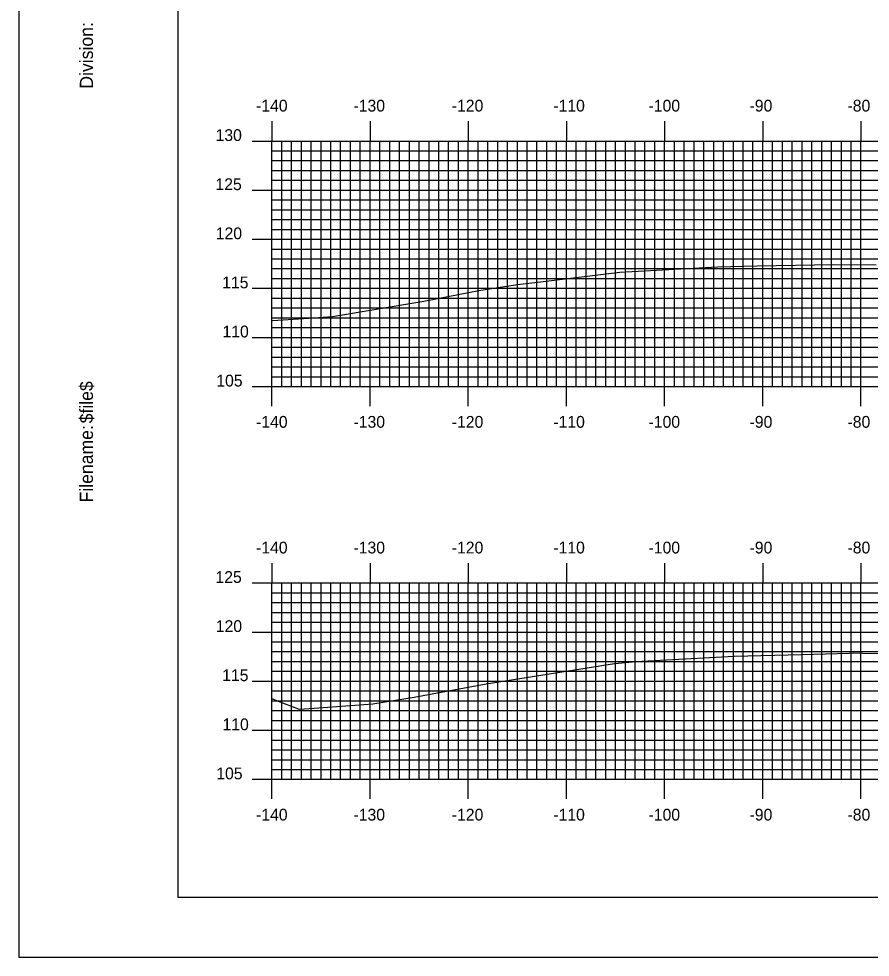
# Model space of a CAD drawing. Extents: x 855468 to 855811, y 366605 to 366825.
# Drawn here: x 855467.8 to 855554.5, y 366604.9 to 366700.5 of the extents above; entities that cross this region are included whole.
import ezdxf

# ---------------------------------------------------------------- set-up
doc = ezdxf.new("R2010")
doc.units = 0
for name, color, linetype in [('BORDER', 7, 'Continuous'), ('H_V ANNOTATION', 7, 'Continuous'), ('M_Roadway_Centerline', 7, 'Continuous'), ('MAJOR', 7, 'Continuous'), ('MINOR', 7, 'Continuous'), ('PLOT BOUNDARY', 7, 'Continuous'), ('S_Roadway_Centerline', 7, 'Continuous')]:
    doc.layers.add(name, color=color, linetype=linetype)

msp = doc.modelspace()

# ---------------------------------------------------------------- linework, layer by layer
at = {"layer": 'BORDER'}
msp.add_lwpolyline([(855483.982, 366611.055), (855803.982, 366611.055), (855803.982, 366821.055), (855483.982, 366821.055)], close=True, dxfattribs=at)
at = {"layer": 'MAJOR'}
for p, q in [((855493.582, 366690.059), (855493.582, 366688.055)), ((855503.582, 366690.059), (855503.582, 366688.055)), ((855513.582, 366690.059), (855513.582, 366688.055)), ((855523.582, 366690.059), (855523.582, 366688.055)), ((855533.582, 366690.059), (855533.582, 366688.055)), ((855543.582, 366690.059), (855543.582, 366688.055)), ((855553.582, 366690.059), (855553.582, 366688.055)), ((855491.578, 366688.055), (855493.582, 366688.055)), ((855493.582, 366688.055), (855773.582, 366688.055)), ((855493.582, 366663.055), (855493.582, 366688.055)), ((855493.582, 366663.055), (855493.582, 366688.055)), ((855493.582, 366688.055), (855773.582, 366688.055)), ((855503.582, 366663.055), (855503.582, 366688.055)), ((855513.582, 366663.055), (855513.582, 366688.055)), ((855523.582, 366663.055), (855523.582, 366688.055)), ((855533.582, 366663.055), (855533.582, 366688.055)), ((855543.582, 366663.055), (855543.582, 366688.055)), ((855553.582, 366663.055), (855553.582, 366688.055)), ((855491.578, 366683.055), (855493.582, 366683.055)), ((855493.582, 366683.055), (855773.582, 366683.055)), ((855491.578, 366678.055), (855493.582, 366678.055)), ((855493.582, 366678.055), (855773.582, 366678.055)), ((855491.578, 366673.055), (855493.582, 366673.055)), ((855493.582, 366673.055), (855773.582, 366673.055)), ((855491.578, 366668.055), (855493.582, 366668.055)), ((855493.582, 366668.055), (855773.582, 366668.055)), ((855491.578, 366663.055), (855493.582, 366663.055)), ((855493.582, 366663.055), (855773.582, 366663.055)), ((855493.582, 366663.055), (855773.582, 366663.055)), ((855493.582, 366661.051), (855493.582, 366663.055)), ((855503.582, 366661.051), (855503.582, 366663.055)), ((855513.582, 366661.051), (855513.582, 366663.055)), ((855523.582, 366661.051), (855523.582, 366663.055)), ((855533.582, 366661.051), (855533.582, 366663.055)), ((855543.582, 366661.051), (855543.582, 366663.055)), ((855553.582, 366661.051), (855553.582, 366663.055)), ((855493.582, 366645.059), (855493.582, 366643.055)), ((855503.582, 366645.059), (855503.582, 366643.055)), ((855513.582, 366645.059), (855513.582, 366643.055)), ((855523.582, 366645.059), (855523.582, 366643.055)), ((855533.582, 366645.059), (855533.582, 366643.055)), ((855543.582, 366645.059), (855543.582, 366643.055)), ((855553.582, 366645.059), (855553.582, 366643.055)), ((855491.578, 366643.055), (855493.582, 366643.055)), ((855493.582, 366643.055), (855773.582, 366643.055)), ((855493.582, 366623.055), (855493.582, 366643.055)), ((855493.582, 366623.055), (855493.582, 366643.055)), ((855493.582, 366643.055), (855773.582, 366643.055)), ((855503.582, 366623.055), (855503.582, 366643.055)), ((855513.582, 366623.055), (855513.582, 366643.055)), ((855523.582, 366623.055), (855523.582, 366643.055)), ((855533.582, 366623.055), (855533.582, 366643.055)), ((855543.582, 366623.055), (855543.582, 366643.055)), ((855553.582, 366623.055), (855553.582, 366643.055)), ((855491.578, 366638.055), (855493.582, 366638.055)), ((855493.582, 366638.055), (855773.582, 366638.055)), ((855491.578, 366633.055), (855493.582, 366633.055)), ((855493.582, 366633.055), (855773.582, 366633.055)), ((855491.578, 366628.055), (855493.582, 366628.055)), ((855493.582, 366628.055), (855773.582, 366628.055)), ((855491.578, 366623.055), (855493.582, 366623.055)), ((855493.582, 366623.055), (855773.582, 366623.055)), ((855493.582, 366623.055), (855773.582, 366623.055)), ((855493.582, 366621.051), (855493.582, 366623.055)), ((855503.582, 366621.051), (855503.582, 366623.055)), ((855513.582, 366621.051), (855513.582, 366623.055)), ((855523.582, 366621.051), (855523.582, 366623.055)), ((855533.582, 366621.051), (855533.582, 366623.055)), ((855543.582, 366621.051), (855543.582, 366623.055)), ((855553.582, 366621.051), (855553.582, 366623.055))]:
    msp.add_line(p, q, dxfattribs=at)
at = {"layer": 'MINOR'}
for p, q in [((855494.582, 366663.055), (855494.582, 366688.055)), ((855495.582, 366663.055), (855495.582, 366688.055)), ((855496.582, 366663.055), (855496.582, 366688.055)), ((855497.582, 366663.055), (855497.582, 366688.055)), ((855498.582, 366663.055), (855498.582, 366688.055)), ((855499.582, 366663.055), (855499.582, 366688.055)), ((855500.582, 366663.055), (855500.582, 366688.055)), ((855501.582, 366663.055), (855501.582, 366688.055)), ((855502.582, 366663.055), (855502.582, 366688.055)), ((855504.582, 366663.055), (855504.582, 366688.055)), ((855505.582, 366663.055), (855505.582, 366688.055)), ((855506.582, 366663.055), (855506.582, 366688.055)), ((855507.582, 366663.055), (855507.582, 366688.055)), ((855508.582, 366663.055), (855508.582, 366688.055)), ((855509.582, 366663.055), (855509.582, 366688.055)), ((855510.582, 366663.055), (855510.582, 366688.055)), ((855511.582, 366663.055), (855511.582, 366688.055)), ((855512.582, 366663.055), (855512.582, 366688.055)), ((855514.582, 366663.055), (855514.582, 366688.055)), ((855515.582, 366663.055), (855515.582, 366688.055)), ((855516.582, 366663.055), (855516.582, 366688.055)), ((855517.582, 366663.055), (855517.582, 366688.055)), ((855518.582, 366663.055), (855518.582, 366688.055)), ((855519.582, 366663.055), (855519.582, 366688.055)), ((855520.582, 366663.055), (855520.582, 366688.055)), ((855521.582, 366663.055), (855521.582, 366688.055)), ((855522.582, 366663.055), (855522.582, 366688.055)), ((855524.582, 366663.055), (855524.582, 366688.055)), ((855525.582, 366663.055), (855525.582, 366688.055)), ((855526.582, 366663.055), (855526.582, 366688.055)), ((855527.582, 366663.055), (855527.582, 366688.055)), ((855528.582, 366663.055), (855528.582, 366688.055)), ((855529.582, 366663.055), (855529.582, 366688.055)), ((855530.582, 366663.055), (855530.582, 366688.055)), ((855531.582, 366663.055), (855531.582, 366688.055)), ((855532.582, 366663.055), (855532.582, 366688.055)), ((855534.582, 366663.055), (855534.582, 366688.055)), ((855535.582, 366663.055), (855535.582, 366688.055)), ((855536.582, 366663.055), (855536.582, 366688.055)), ((855537.582, 366663.055), (855537.582, 366688.055)), ((855538.582, 366663.055), (855538.582, 366688.055)), ((855539.582, 366663.055), (855539.582, 366688.055)), ((855540.582, 366663.055), (855540.582, 366688.055)), ((855541.582, 366663.055), (855541.582, 366688.055)), ((855542.582, 366663.055), (855542.582, 366688.055)), ((855544.582, 366663.055), (855544.582, 366688.055)), ((855545.582, 366663.055), (855545.582, 366688.055)), ((855546.582, 366663.055), (855546.582, 366688.055)), ((855547.582, 366663.055), (855547.582, 366688.055)), ((855548.582, 366663.055), (855548.582, 366688.055)), ((855549.582, 366663.055), (855549.582, 366688.055)), ((855550.582, 366663.055), (855550.582, 366688.055)), ((855551.582, 366663.055), (855551.582, 366688.055)), ((855552.582, 366663.055), (855552.582, 366688.055)), ((855493.582, 366687.055), (855773.582, 366687.055)), ((855493.582, 366687.055), (855495.586, 366687.055)), ((855493.582, 366686.055), (855773.582, 366686.055)), ((855493.582, 366686.055), (855495.586, 366686.055)), ((855493.582, 366685.055), (855773.582, 366685.055)), ((855493.582, 366685.055), (855495.586, 366685.055)), ((855493.582, 366684.055), (855773.582, 366684.055)), ((855493.582, 366684.055), (855495.586, 366684.055)), ((855493.582, 366682.055), (855773.582, 366682.055)), ((855493.582, 366682.055), (855495.586, 366682.055)), ((855493.582, 366681.055), (855773.582, 366681.055)), ((855493.582, 366681.055), (855495.586, 366681.055)), ((855493.582, 366680.055), (855773.582, 366680.055)), ((855493.582, 366680.055), (855495.586, 366680.055)), ((855493.582, 366679.055), (855773.582, 366679.055)), ((855493.582, 366679.055), (855495.586, 366679.055)), ((855493.582, 366677.055), (855773.582, 366677.055)), ((855493.582, 366677.055), (855495.586, 366677.055)), ((855493.582, 366676.055), (855773.582, 366676.055)), ((855493.582, 366676.055), (855495.586, 366676.055)), ((855493.582, 366675.055), (855773.582, 366675.055)), ((855493.582, 366675.055), (855495.586, 366675.055)), ((855493.582, 366674.055), (855773.582, 366674.055)), ((855493.582, 366674.055), (855495.586, 366674.055)), ((855493.582, 366672.055), (855773.582, 366672.055)), ((855493.582, 366672.055), (855495.586, 366672.055)), ((855493.582, 366671.055), (855773.582, 366671.055)), ((855493.582, 366671.055), (855495.586, 366671.055)), ((855493.582, 366670.055), (855773.582, 366670.055)), ((855493.582, 366670.055), (855495.586, 366670.055)), ((855493.582, 366669.055), (855773.582, 366669.055)), ((855493.582, 366669.055), (855495.586, 366669.055)), ((855493.582, 366667.055), (855773.582, 366667.055)), ((855493.582, 366667.055), (855495.586, 366667.055)), ((855493.582, 366666.055), (855773.582, 366666.055)), ((855493.582, 366666.055), (855495.586, 366666.055)), ((855493.582, 366665.055), (855773.582, 366665.055)), ((855493.582, 366665.055), (855495.586, 366665.055)), ((855493.582, 366664.055), (855773.582, 366664.055)), ((855493.582, 366664.055), (855495.586, 366664.055)), ((855494.582, 366623.055), (855494.582, 366643.055)), ((855495.582, 366623.055), (855495.582, 366643.055)), ((855496.582, 366623.055), (855496.582, 366643.055)), ((855497.582, 366623.055), (855497.582, 366643.055)), ((855498.582, 366623.055), (855498.582, 366643.055)), ((855499.582, 366623.055), (855499.582, 366643.055)), ((855500.582, 366623.055), (855500.582, 366643.055)), ((855501.582, 366623.055), (855501.582, 366643.055)), ((855502.582, 366623.055), (855502.582, 366643.055)), ((855504.582, 366623.055), (855504.582, 366643.055)), ((855505.582, 366623.055), (855505.582, 366643.055)), ((855506.582, 366623.055), (855506.582, 366643.055)), ((855507.582, 366623.055), (855507.582, 366643.055)), ((855508.582, 366623.055), (855508.582, 366643.055)), ((855509.582, 366623.055), (855509.582, 366643.055)), ((855510.582, 366623.055), (855510.582, 366643.055)), ((855511.582, 366623.055), (855511.582, 366643.055)), ((855512.582, 366623.055), (855512.582, 366643.055)), ((855514.582, 366623.055), (855514.582, 366643.055)), ((855515.582, 366623.055), (855515.582, 366643.055)), ((855516.582, 366623.055), (855516.582, 366643.055)), ((855517.582, 366623.055), (855517.582, 366643.055)), ((855518.582, 366623.055), (855518.582, 366643.055)), ((855519.582, 366623.055), (855519.582, 366643.055)), ((855520.582, 366623.055), (855520.582, 366643.055)), ((855521.582, 366623.055), (855521.582, 366643.055)), ((855522.582, 366623.055), (855522.582, 366643.055)), ((855524.582, 366623.055), (855524.582, 366643.055)), ((855525.582, 366623.055), (855525.582, 366643.055)), ((855526.582, 366623.055), (855526.582, 366643.055)), ((855527.582, 366623.055), (855527.582, 366643.055)), ((855528.582, 366623.055), (855528.582, 366643.055)), ((855529.582, 366623.055), (855529.582, 366643.055)), ((855530.582, 366623.055), (855530.582, 366643.055)), ((855531.582, 366623.055), (855531.582, 366643.055)), ((855532.582, 366623.055), (855532.582, 366643.055)), ((855534.582, 366623.055), (855534.582, 366643.055)), ((855535.582, 366623.055), (855535.582, 366643.055)), ((855536.582, 366623.055), (855536.582, 366643.055)), ((855537.582, 366623.055), (855537.582, 366643.055)), ((855538.582, 366623.055), (855538.582, 366643.055)), ((855539.582, 366623.055), (855539.582, 366643.055)), ((855540.582, 366623.055), (855540.582, 366643.055)), ((855541.582, 366623.055), (855541.582, 366643.055)), ((855542.582, 366623.055), (855542.582, 366643.055)), ((855544.582, 366623.055), (855544.582, 366643.055)), ((855545.582, 366623.055), (855545.582, 366643.055)), ((855546.582, 366623.055), (855546.582, 366643.055)), ((855547.582, 366623.055), (855547.582, 366643.055)), ((855548.582, 366623.055), (855548.582, 366643.055)), ((855549.582, 366623.055), (855549.582, 366643.055)), ((855550.582, 366623.055), (855550.582, 366643.055)), ((855551.582, 366623.055), (855551.582, 366643.055)), ((855552.582, 366623.055), (855552.582, 366643.055)), ((855493.582, 366642.055), (855773.582, 366642.055)), ((855493.582, 366642.055), (855495.586, 366642.055)), ((855493.582, 366641.055), (855773.582, 366641.055)), ((855493.582, 366641.055), (855495.586, 366641.055)), ((855493.582, 366640.055), (855773.582, 366640.055)), ((855493.582, 366640.055), (855495.586, 366640.055)), ((855493.582, 366639.055), (855773.582, 366639.055)), ((855493.582, 366639.055), (855495.586, 366639.055)), ((855493.582, 366637.055), (855773.582, 366637.055)), ((855493.582, 366637.055), (855495.586, 366637.055)), ((855493.582, 366636.055), (855773.582, 366636.055)), ((855493.582, 366636.055), (855495.586, 366636.055)), ((855493.582, 366635.055), (855773.582, 366635.055)), ((855493.582, 366635.055), (855495.586, 366635.055)), ((855493.582, 366634.055), (855773.582, 366634.055)), ((855493.582, 366634.055), (855495.586, 366634.055)), ((855493.582, 366632.055), (855773.582, 366632.055)), ((855493.582, 366632.055), (855495.586, 366632.055)), ((855493.582, 366631.055), (855773.582, 366631.055)), ((855493.582, 366631.055), (855495.586, 366631.055)), ((855493.582, 366630.055), (855773.582, 366630.055)), ((855493.582, 366630.055), (855495.586, 366630.055)), ((855493.582, 366629.055), (855773.582, 366629.055)), ((855493.582, 366629.055), (855495.586, 366629.055)), ((855493.582, 366627.055), (855773.582, 366627.055)), ((855493.582, 366627.055), (855495.586, 366627.055)), ((855493.582, 366626.055), (855773.582, 366626.055)), ((855493.582, 366626.055), (855495.586, 366626.055)), ((855493.582, 366625.055), (855773.582, 366625.055)), ((855493.582, 366625.055), (855495.586, 366625.055)), ((855493.582, 366624.055), (855773.582, 366624.055)), ((855493.582, 366624.055), (855495.586, 366624.055))]:
    msp.add_line(p, q, dxfattribs=at)
at = {"layer": 'PLOT BOUNDARY'}
msp.add_lwpolyline([(855467.796, 366604.937), (855807.796, 366604.937), (855807.796, 366824.937), (855467.796, 366824.937)], close=True, dxfattribs=at)
at = {"layer": 'S_Roadway_Centerline'}
for points in [[(855493.582, 366669.805), (855493.673, 366669.78), (855497.861, 366670.036), (855499.763, 366670.2), (855509.051, 366671.735), (855514.665, 366672.833), (855518.612, 366673.444), (855520.933, 366673.715), (855529.005, 366674.715), (855538.361, 366675.21), (855538.954, 366675.247), (855543.005, 366675.357), (855550.769, 366675.493), (855555.125, 366675.447)], [(855493.582, 366631.282), (855494.228, 366631.029), (855496.361, 366630.192), (855498.356, 366630.337), (855503.864, 366630.75), (855508.081, 366631.421), (855515.42, 366632.792), (855528.465, 366634.841), (855528.888, 366634.894), (855530.649, 366635.046), (855533.158, 366635.202), (855540.661, 366635.588), (855547.569, 366635.778), (855552.371, 366635.909), (855552.845, 366635.925), (855553.765, 366635.91), (855564.742, 366635.682)]]:
    msp.add_lwpolyline(points, dxfattribs=at)

# ---------------------------------------------------------------- texts
at = {"layer": 'BORDER'}
for s, p in [('Division:', (855475.352, 366693.387)), ('$file$', (855475.352, 366659.306)), ('Filename:', (855475.352, 366651.252))]:
    msp.add_text(s, height=1.3392, rotation=90, dxfattribs=at).set_placement(p)
at = {"layer": 'H_V ANNOTATION'}
for s, p in [('-140', (855491.966, 366691.055)), ('-130', (855501.891, 366691.055)), ('-120', (855511.902, 366691.055)), ('-110', (855522.245, 366691.055)), ('-100', (855531.945, 366691.055)), ('-90', (855542.234, 366691.055)), ('-80', (855552.212, 366691.055)), ('130', (855487.842, 366688.055)), ('125', (855487.831, 366683.055)), ('120', (855487.864, 366678.055)), ('115', (855488.517, 366673.055)), ('110', (855488.549, 366668.055)), ('105', (855487.917, 366663.055)), ('-140', (855491.966, 366658.855)), ('-130', (855501.891, 366658.855)), ('-120', (855511.902, 366658.855)), ('-110', (855522.245, 366658.855)), ('-100', (855531.945, 366658.855)), ('-90', (855542.234, 366658.855)), ('-80', (855552.212, 366658.855)), ('-140', (855491.966, 366646.055)), ('-130', (855501.891, 366646.055)), ('-120', (855511.902, 366646.055)), ('-110', (855522.245, 366646.055)), ('-100', (855531.945, 366646.055)), ('-90', (855542.234, 366646.055)), ('-80', (855552.212, 366646.055)), ('125', (855487.831, 366643.055)), ('120', (855487.864, 366638.055)), ('115', (855488.517, 366633.055)), ('110', (855488.549, 366628.055)), ('105', (855487.917, 366623.055)), ('-140', (855491.966, 366618.855)), ('-130', (855501.891, 366618.855)), ('-120', (855511.902, 366618.855)), ('-110', (855522.245, 366618.855)), ('-100', (855531.945, 366618.855)), ('-90', (855542.234, 366618.855)), ('-80', (855552.212, 366618.855))]:
    msp.add_text(s, height=1.2, dxfattribs=at).set_placement(p)
at = {"layer": 'M_Roadway_Centerline'}
for s, p in [('C', (855550.764, 366675.493)), ('L', (855550.769, 366675.486)), ('C', (855552.84, 366635.925)), ('L', (855552.845, 366635.917))]:
    msp.add_text(s, height=0.0146, dxfattribs=at).set_placement(p)
at = {"layer": 'MAJOR'}
for p in [(855493.574, 366663.055), (855493.574, 366623.055)]:
    msp.add_text('-', height=0.012, dxfattribs=at).set_placement(p)

doc.saveas('drawing.dxf')
